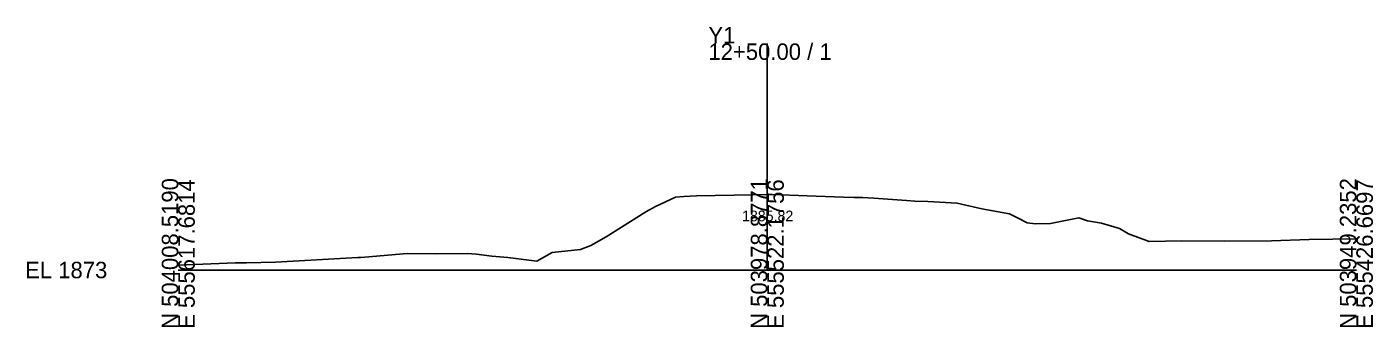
# Model space of a CAD drawing. Extents: x -26 to 1503, y -10 to 5015.
# Drawn here: x -25.7 to 202.8, y 2490.3 to 2541.3 of the extents above; entities that cross this region are included whole.
import ezdxf

# ---------------------------------------------------------------- set-up
doc = ezdxf.new("R2010")
doc.units = 0
for name, color, linetype in [('Default', 7, 'Continuous'), ('Exist Cross Section Cell', 7, 'Continuous'), ('Exist XS Center Line Elevation Label', 7, 'Continuous'), ('Exist XS Ground Line', 7, 'Continuous')]:
    doc.layers.add(name, color=color, linetype=linetype)

msp = doc.modelspace()

# ---------------------------------------------------------------- linework, layer by layer
at = {"layer": 'Exist Cross Section Cell'}
for p, q in [((100, 2500), (100, 2538.49)), ((0, 2500), (100, 2500)), ((100, 2500), (200, 2500))]:
    msp.add_line(p, q, dxfattribs=at)
at = {"layer": 'Exist XS Ground Line'}
for p, q in [((81, 2510.81), (84.39, 2512.37)), ((84.39, 2512.37), (85.85, 2512.46)), ((85.85, 2512.46), (87.97, 2512.62)), ((87.97, 2512.62), (97.55, 2512.78)), ((97.55, 2512.78), (100, 2512.82)), ((100, 2512.82), (100.83, 2512.83)), ((100.83, 2512.83), (106.78, 2512.58)), ((106.78, 2512.58), (112.95, 2512.39)), ((112.95, 2512.39), (114.76, 2512.34)), ((114.76, 2512.34), (116.18, 2512.29)), ((116.18, 2512.29), (118.11, 2512.19)), ((118.11, 2512.19), (123.64, 2511.79)), ((123.64, 2511.79), (125.03, 2511.7)), ((125.03, 2511.7), (127.27, 2511.62)), ((127.27, 2511.62), (132.21, 2511.36)), ((72.67, 2505.66), (79.36, 2509.9)), ((79.36, 2509.9), (81, 2510.81)), ((132.21, 2511.36), (136.44, 2510.42)), ((136.44, 2510.42), (141.11, 2509.57)), ((141.11, 2509.57), (142.61, 2508.81)), ((142.61, 2508.81), (144.12, 2508.03)), ((144.12, 2508.03), (145.52, 2507.85)), ((145.52, 2507.85), (148.05, 2507.92)), ((148.05, 2507.92), (152.86, 2508.88)), ((152.86, 2508.88), (154.37, 2508.33)), ((154.37, 2508.33), (156.76, 2507.97)), ((156.76, 2507.97), (159.78, 2507.08)), ((159.78, 2507.08), (161.31, 2506.15)), ((70.06, 2504.16), (72.67, 2505.66)), ((161.31, 2506.15), (164.85, 2504.84)), ((164.85, 2504.84), (170.37, 2504.97)), ((170.37, 2504.97), (177.68, 2504.91)), ((177.68, 2504.91), (185.59, 2504.93)), ((185.59, 2504.93), (192.01, 2505.2)), ((192.01, 2505.2), (200, 2505.3)), ((31.66, 2502.2), (38.84, 2502.8)), ((38.84, 2502.8), (43.8, 2502.75)), ((43.8, 2502.75), (49.07, 2502.79)), ((49.07, 2502.79), (50.62, 2502.7)), ((50.62, 2502.7), (53.26, 2502.36)), ((60.88, 2501.52), (63.5, 2502.98)), ((63.5, 2502.98), (68.3, 2503.48)), ((68.3, 2503.48), (70.06, 2504.16)), ((0, 2500.84), (9.73, 2501.21)), ((9.73, 2501.21), (11.6, 2501.2)), ((11.6, 2501.2), (16.5, 2501.35)), ((16.5, 2501.35), (30.47, 2502.1)), ((30.47, 2502.1), (30.95, 2502.14)), ((30.95, 2502.14), (31.66, 2502.2)), ((53.26, 2502.36), (55.94, 2502.12)), ((55.94, 2502.12), (60.88, 2501.52))]:
    msp.add_line(p, q, dxfattribs=at)

# ---------------------------------------------------------------- texts
at = {"layer": 'Default'}
msp.add_text('-', height=0.0001, dxfattribs=at).set_placement((0, 2500))
at = {"layer": 'Exist Cross Section Cell'}
for s, p in [('Y1', (90, 2538.49)), ('12+50.00 / 1', (90, 2535.69)), ('EL 1873', (-26, 2498.6))]:
    msp.add_text(s, height=2.8, dxfattribs=at).set_placement(p)
for s, p in [('N 504008.5190', (0, 2490)), ('E 555617.6814', (2.8, 2490)), ('N 503978.8771', (100, 2490)), ('E 555522.1756', (102.8, 2490)), ('N 503949.2352', (200, 2490)), ('E 555426.6697', (202.8, 2490))]:
    msp.add_text(s, height=2.8, rotation=90, dxfattribs=at).set_placement(p)
at = {"layer": 'Exist XS Center Line Elevation Label'}
msp.add_text('1885.82', height=1.8, dxfattribs=at).set_placement((95.71, 2508.29))

doc.saveas('drawing.dxf')
